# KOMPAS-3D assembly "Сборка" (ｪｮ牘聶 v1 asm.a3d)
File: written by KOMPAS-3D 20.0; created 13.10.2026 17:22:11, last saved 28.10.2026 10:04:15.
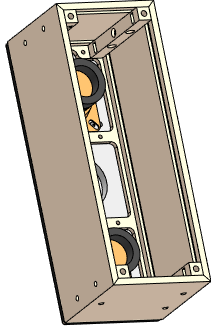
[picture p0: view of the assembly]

Document properties: Полное имя файла: D:\RicWork\Project-EPS32\box_compas\корпус\корпус v1 asm.a3d

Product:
- Part/product: Сборка
    Масса: 1.6131
  - Component [detail]: Деталь  | Материал: Фанера, сосна,ФСФ ВВ/С  ГОСТ 3916.2-2018 (density 500 kg/m3); Масса: 0.0392075; source file: стенка80х216х5 down.m3d
  - Component [detail]: Деталь  | qty 4  | Масса: 0.0499424; source file: Panel_стяжка.m3d
  - Component [detail]: Деталь  | qty 2  | Материал: Фанера, сосна,ФСФ ВВ/С  ГОСТ 3916.2-2018 (density 500 kg/m3); Масса: 0.0139089; source file: стенка80х80х5.m3d
  - Component [detail]: Деталь  | Материал: Фанера, сосна,ФСФ ВВ/С  ГОСТ 3916.2-2018 (density 500 kg/m3); Масса: 0.0392703; source file: стенка80х216х5 up.m3d
  - Component [assembly]: Сборка  | Масса: 1.30703; source file: Front_Panel asm.a3d

Referenced files in D:\RicWork\Project-EPS32\box_compas\корпус\: стенка80х216х5 down.m3d, Panel_стяжка.m3d, стенка80х80х5.m3d, стенка80х216х5 up.m3d, Front_Panel asm.a3d
Referenced files in D:\myProjects\Progect_esp32\box_compas\корпус\: Panel_стяжка.m3d, стенка80х80х5.m3d
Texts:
  Деталь (1)
  Деталь (2)
  Деталь (3)
  Деталь (4)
